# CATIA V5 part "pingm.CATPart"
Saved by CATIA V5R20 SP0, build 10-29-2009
Part number: 屏幕
Bounding box of the stored display mesh (mm): x -2 to 2, y -50 to 50, z -37 to 37
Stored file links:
  C:\Users\GBH\Desktop\电脑\pingm.CATPart
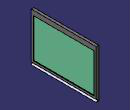
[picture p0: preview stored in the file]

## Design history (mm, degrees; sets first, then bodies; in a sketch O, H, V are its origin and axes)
Body1 (main body)
  Sketch1 on yz-plane, origin (0, 0, 0), H (0, 1, 0), V (0, 0, 1)
    line L1 (50, 37) -> (50, -37)
    line L2 (50, -37) -> (-50, -37)
    line L3 (-50, -37) -> (-50, 37)
    line L4 (-50, 37) -> (50, 37)
    length L4 = 100
    length L3 = 74
    vertical: L1 V, L3 V
    horizontal: L2 H, L4 H
    equidistance: L1 L3 O, L2 L4 O
  Pad1: profile Sketch1, direction (1, 0, 0), length 2, mirrored extent
  Sketch2 on end face of Pad1, origin (2, 0, 0), H (0, 1, 0), V (0, 0, 1)
    line L1 (46.8326, 29.9344) -> (46.8326, -29.9344)
    line L2 (46.8326, -29.9344) -> (-46.8326, -29.9344)
    line L3 (-46.8326, -29.9344) -> (-46.8326, 29.9344)
    line L4 (-46.8326, 29.9344) -> (46.8326, 29.9344)
    vertical: L1 V, L3 V
    horizontal: L2 H, L4 H
    equidistance: L1 L3 O, L2 L4 O
  Pocket1: profile Sketch2, direction (-1, 0, 0), length 1
  Sketch3 on face of Pad1 from Sketch1.L1, origin (0, 50, 0), H (-1, 0, 0), V (0, 0, 1)
    arc A1 centre (-2, -35) radius 2 from (-2, -37) to (-2, -33) ccw
    point P2 (0, -35)
    radius A1 = 2
    coincidence: A1 P2, P2 V
  Pocket2: profile Sketch3, direction (0, -1, 0), length 100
